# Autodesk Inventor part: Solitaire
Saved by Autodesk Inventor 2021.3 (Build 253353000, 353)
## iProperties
Created: 2022-04
Part Number: Solitaire
Material: Generic
Document SubType Name: Modeling
Designer: Administrator
Density: 1 g/cm^3
Appearance: Default
Title: Solitaire v10
Author: Administrator
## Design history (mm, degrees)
feature "Solitaire_"
feature "Socket Body"
feature "Shade Ring"
feature "Shade Ring +Collar"
feature "Socket"
feature "Canopy"
feature "Metal Strain Relief"
feature "Fabric Cord (1)"
feature "Stem (Threaded)"
feature "Cap (Threaded)"
feature "G30 - Bulb"
feature "G30 - E26"
body "Solid1"
body "Solid2"
body "Solid3"
body "Solid4"
body "Solid5"
body "Solid6"
body "Solid7"
body "Solid8"
body "Solid9"
body "Solid10"
body "Solid11"
body "Solid12"
